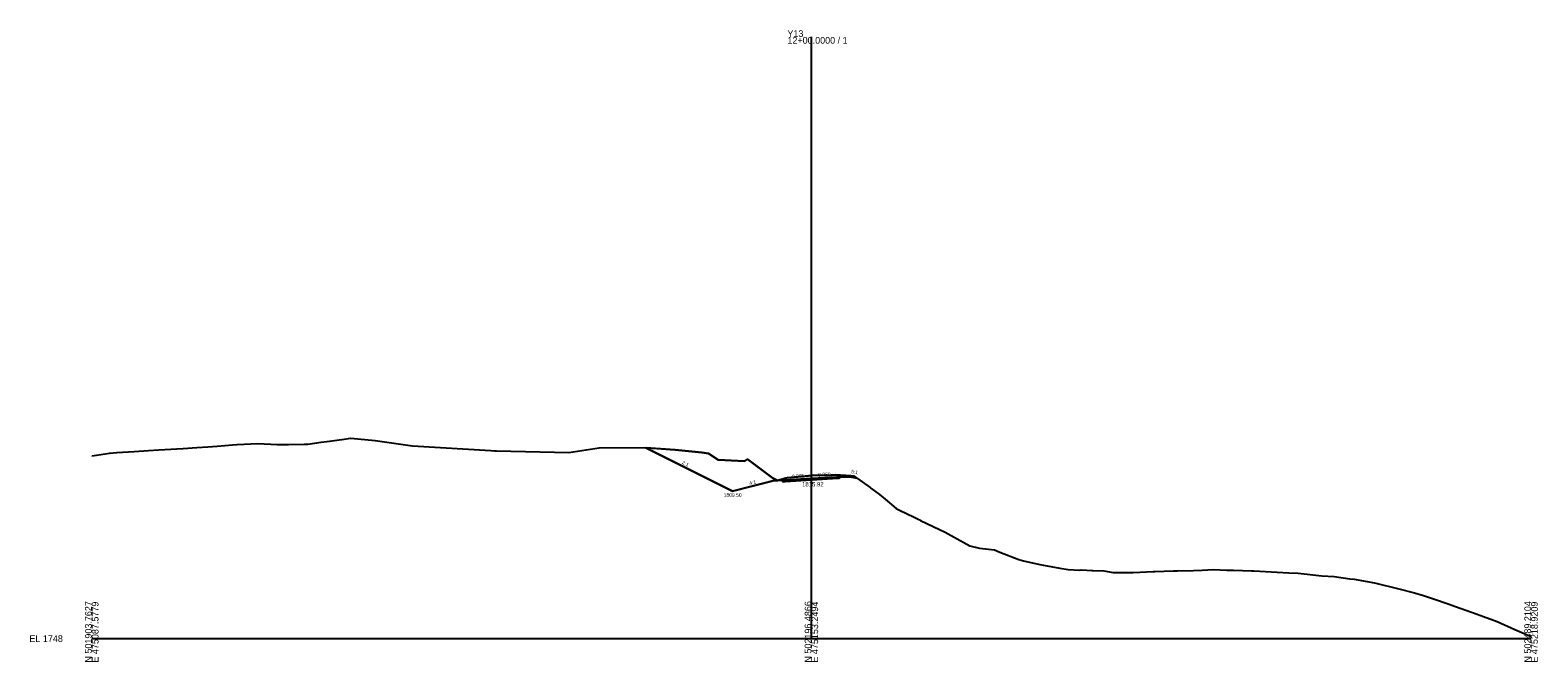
# Model space of a CAD drawing. Extents: x -126 to 503, y -10 to 2750.
# Drawn here: x -126 to 503, y 1990 to 2254 of the extents above; entities that cross this region are included whole.
import ezdxf

# ---------------------------------------------------------------- set-up
doc = ezdxf.new("R2010")
doc.units = 0
for name, color, linetype in [('Exist Cross Section Cell', 7, 'Continuous'), ('Exist XS Center Line Elevation Label', 7, 'Continuous'), ('Exist XS Ground Line', 7, 'Continuous'), ('Prop XS Ditch Slope Text', 7, 'Continuous'), ('Prop XS Ditch Standard Text', 7, 'Continuous'), ('Prop XS Dump Level', 7, 'Continuous'), ('Prop XS Earthwork Shape', 7, 'Continuous'), ('Prop XS EOT Tick Mark', 7, 'Continuous'), ('Prop XS Finish Grade', 7, 'Continuous'), ('Prop XS Finish Grade Earthwork', 7, 'Continuous'), ('Prop XS Finish Grade Pavement', 7, 'Continuous'), ('Prop XS Hydro Typical Ditch Data', 7, 'Continuous'), ('Prop XS Pvmt Edge Slope', 7, 'Continuous'), ('Prop XS SE Text', 7, 'Continuous'), ('Prop XS Shoulder Borrow Shape', 7, 'Continuous'), ('Prop XS Side Slope Text', 7, 'Continuous'), ('Prop XS Subgrade Earthwork', 7, 'Continuous')]:
    doc.layers.add(name, color=color, linetype=linetype)

msp = doc.modelspace()

# ---------------------------------------------------------------- linework, layer by layer
at = {"layer": 'Exist Cross Section Cell'}
for p, q in [((200, 2000), (200, 2250.78)), ((-100, 2000), (200, 2000)), ((200, 2000), (500, 2000))]:
    msp.add_line(p, q, dxfattribs=at)
at = {"layer": 'Exist XS Ground Line'}
msp.add_lwpolyline([(-100, 2076.15), (-97.97, 2076.41), (-92.57, 2077.27), (-89.6, 2077.6), (-82.33, 2077.99), (-76.37, 2078.38), (-72.09, 2078.64), (-64.5, 2079.09), (-61.84, 2079.23), (-56.14, 2079.66), (-51.59, 2079.89), (-47.77, 2080.27), (-41.35, 2080.77), (-39.41, 2080.94), (-30.78, 2081.37), (-22.68, 2080.89), (-20.85, 2080.91), (-17.97, 2080.94), (-11.52, 2081.01), (-10.6, 2080.99), (-9.98, 2081.02), (-4.44, 2081.82), (-0.92, 2082.32), (5.17, 2083.19), (6.98, 2083.45), (8, 2083.59), (18.13, 2082.58), (33.64, 2080.39), (66.31, 2078.4), (67.86, 2078.27), (68.68, 2078.29), (98.87, 2077.6), (111.45, 2079.53), (129.9, 2079.65), (143.14, 2078.65), (154.27, 2077.54), (157.07, 2077.22), (161.16, 2074.46), (172.15, 2073.98), (173.35, 2074.79), (183.94, 2066.85), (185.8, 2065.87), (189.38, 2066.82), (189.93, 2066.96), (191.39, 2067.09), (200.27, 2067.95), (208.26, 2068.19), (210.07, 2068.24), (216.43, 2067.84), (217.82, 2067.72), (224.52, 2062.98), (224.84, 2062.74), (228.37, 2060.09), (230.8, 2058.06), (235.29, 2054.29), (236.67, 2053.59), (242.81, 2050.62), (245.04, 2049.55), (245.54, 2049.29), (253.4, 2045.46), (255.78, 2044.38), (259.54, 2042.32), (266.02, 2038.66), (270.13, 2037.76), (276.27, 2037.02), (278.5, 2036.06), (286.52, 2032.95), (288.4, 2032.48), (295.23, 2030.86), (296.76, 2030.64), (303.59, 2029.42), (307.01, 2028.83), (311.96, 2028.54), (312.42, 2028.69), (314.82, 2028.59), (316.97, 2028.37), (317.42, 2028.33), (321.89, 2028.22), (325.79, 2027.55), (332.14, 2027.49), (334.16, 2027.5), (342.53, 2027.99), (343.16, 2028.02), (350.91, 2028.19), (352.64, 2028.27), (359.28, 2028.38), (362.9, 2028.55), (367.65, 2028.77), (373.15, 2028.53), (376.02, 2028.56), (383.4, 2028.23), (384.4, 2028.26), (399.06, 2027.37), (402.96, 2027.27), (412.82, 2026.1), (417.89, 2025.84), (424.4, 2024.91), (426.26, 2024.72), (434.68, 2023.2), (444.9, 2020.77), (451.37, 2019.09), (455.15, 2017.91), (459.75, 2016.43), (465.4, 2014.45), (468.12, 2013.58), (475.65, 2010.9), (480.23, 2009.23), (485.9, 2007.12), (493.24, 2003.84), (496.15, 2002.47), (500, 2000.82)], dxfattribs=at)
at = {"layer": 'Prop XS Dump Level'}
for p, q in [((189, 2066.11), (200, 2066.83)), ((200, 2066.83), (211, 2067.49))]:
    msp.add_line(p, q, dxfattribs=at)
at = {"layer": 'Prop XS Earthwork Shape'}
msp.add_lwpolyline([(211, 2066.82), (211.63, 2066.86), (212.26, 2067.49), (216, 2067.49), (218.99, 2066.89), (217.82, 2067.72), (216.43, 2067.84), (210.07, 2068.24), (208.26, 2068.19), (200.27, 2067.95), (191.39, 2067.09), (189.93, 2066.96), (189.38, 2066.82), (185.8, 2065.87), (183.94, 2066.85), (173.35, 2074.79), (172.15, 2073.98), (161.16, 2074.46), (157.07, 2077.22), (154.27, 2077.54), (143.14, 2078.65), (131.02, 2079.56), (167.14, 2061.5), (184, 2065.71), (187.68, 2066.01), (188.29, 2065.4), (189, 2065.45), (200, 2066.16)], close=True, dxfattribs=at)
at = {"layer": 'Prop XS EOT Tick Mark'}
for p, q in [((211, 2067.49), (211, 2068.49)), ((189, 2066.11), (189, 2067.11))]:
    msp.add_line(p, q, dxfattribs=at)
at = {"layer": 'Prop XS Finish Grade'}
for p, q in [((189, 2066.11), (187.68, 2066.01)), ((211, 2067.49), (212.26, 2067.49))]:
    msp.add_line(p, q, dxfattribs=at)
at = {"layer": 'Prop XS Finish Grade Earthwork'}
for p, q in [((167.14, 2061.5), (131.02, 2079.56)), ((184, 2065.71), (167.14, 2061.5)), ((187.68, 2066.01), (184, 2065.71)), ((212.26, 2067.49), (216, 2067.49)), ((216, 2067.49), (218.99, 2066.89))]:
    msp.add_line(p, q, dxfattribs=at)
at = {"layer": 'Prop XS Finish Grade Pavement'}
for p, q in [((189, 2066.11), (200, 2066.83)), ((200, 2066.83), (211, 2067.49))]:
    msp.add_line(p, q, dxfattribs=at)
at = {"layer": 'Prop XS Hydro Typical Ditch Data'}
for p, q in [((167.14, 2061.5), (131.02, 2079.56)), ((184, 2065.71), (176, 2063.71))]:
    msp.add_line(p, q, dxfattribs=at)
at = {"layer": 'Prop XS Pvmt Edge Slope'}
for p, q in [((189, 2066.11), (188.29, 2065.4)), ((211, 2067.49), (211.63, 2066.86))]:
    msp.add_line(p, q, dxfattribs=at)
at = {"layer": 'Prop XS Shoulder Borrow Shape'}
for points in [[(189, 2066.11), (187.68, 2066.01), (188.29, 2065.4)], [(211, 2067.49), (212.26, 2067.49), (211.63, 2066.86)]]:
    msp.add_lwpolyline(points, close=True, dxfattribs=at)
at = {"layer": 'Prop XS Subgrade Earthwork'}
for p, q in [((188.29, 2065.4), (187.68, 2066.01)), ((189, 2065.45), (188.29, 2065.4)), ((200, 2066.16), (189, 2065.45)), ((211, 2066.82), (200, 2066.16)), ((211, 2066.82), (211.63, 2066.86)), ((211.63, 2066.86), (212.26, 2067.49))]:
    msp.add_line(p, q, dxfattribs=at)

# ---------------------------------------------------------------- texts
at = {"layer": 'Exist Cross Section Cell'}
for s, p in [('Y13', (190, 2250.78)), ('12+00.0000 / 1', (190, 2247.98)), ('EL 1748', (-126, 1998.6))]:
    msp.add_text(s, height=2.8, dxfattribs=at).set_placement(p)
for s, p in [('N 501903.7627', (-100, 1990)), ('E 475087.5779', (-97.2, 1990)), ('N 502196.4866', (200, 1990)), ('E 475153.2494', (202.8, 1990)), ('N 502489.2104', (500, 1990)), ('E 475218.9209', (502.8, 1990))]:
    msp.add_text(s, height=2.8, rotation=90, dxfattribs=at).set_placement(p)
at = {"layer": 'Exist XS Center Line Elevation Label'}
msp.add_text('1815.92', height=1.8, dxfattribs=at).set_placement((196.11, 2063.45))
at = {"layer": 'Prop XS Ditch Slope Text'}
msp.add_text('4:1', height=1.5, rotation=14.03624, dxfattribs=at).set_placement((174.3, 2063.92))
at = {"layer": 'Prop XS Ditch Standard Text'}
msp.add_text('1809.50', height=1.5, dxfattribs=at).set_placement((163.43, 2059.1))
at = {"layer": 'Prop XS Dump Level'}
for p in [(184, 2065.67), (216, 2067.45)]:
    msp.add_text('Case1', height=0.04, dxfattribs=at).set_placement(p)
at = {"layer": 'Prop XS SE Text'}
for s, rotation, p in [('0.065', 3.71543, (191.9, 2066.8)), ('0.060', 3.43363, (202.88, 2067.5))]:
    msp.add_text(s, height=1.5, rotation=rotation, dxfattribs=at).set_placement(p)
at = {"layer": 'Prop XS Side Slope Text'}
for s, rotation, p in [('2:1', 333.43495, (145.89, 2072.94)), ('5:1', 350.53768, (216.48, 2068.93))]:
    msp.add_text(s, height=1.5, rotation=rotation, dxfattribs=at).set_placement(p)

doc.saveas('drawing.dxf')
